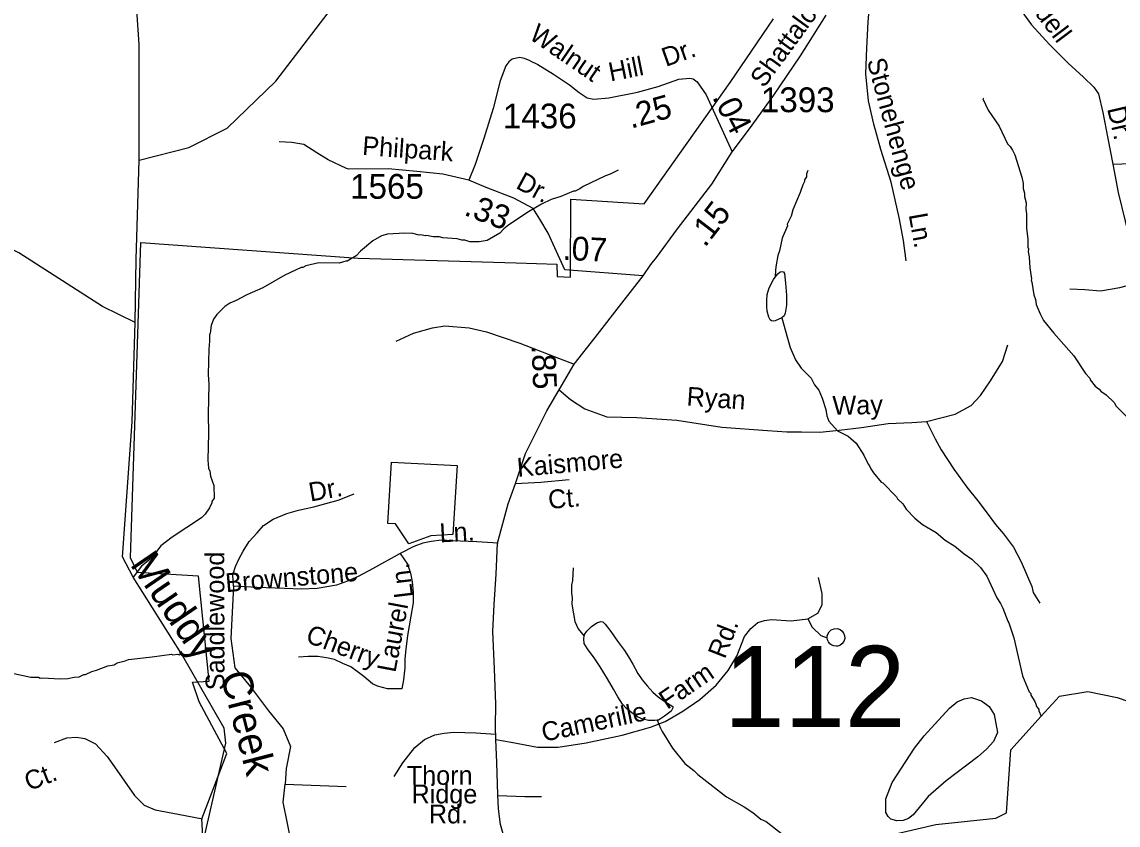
# Model space of a CAD drawing. Extents: x 1547597 to 1699558, y 810033 to 920809.
# Drawn here: x 1600633 to 1606161, y 869495 to 873547 of the extents above; entities that cross this region are included whole.
import ezdxf

# ---------------------------------------------------------------- set-up
doc = ezdxf.new("R2010")
doc.units = 0
for name, color, linetype in [('Exist Boundary Political City Limit New', 7, 'Continuous'), ('Exist Boundary Political City Limit New Hole', 7, 'Continuous'), ('Exist Hydrographic Creek Single Shore', 7, 'Continuous'), ('Exist Hydrographic Creek Single Shore Label', 7, 'Continuous'), ('Exist Hydrographic Misc Water Feature', 7, 'Continuous'), ('Exist Road Non-System Type 51', 7, 'Continuous'), ('Exist Road Non-System Type 51 Label', 7, 'Continuous'), ('Exist Road Secondary Mileage Hundredths English Label', 7, 'Continuous'), ('Exist Road Secondary Structure Standard Bridge Number Label', 7, 'Continuous'), ('Exist Road Secondary Type 51 Attributed', 7, 'Continuous'), ('Exist Road Secondary Type 51 Label', 7, 'Continuous'), ('Exist Road Secondary Type 51 Number Label', 7, 'Continuous'), ('Map Preparation Boundary City Limit Buffer Line', 7, 'Continuous')]:
    doc.layers.add(name, color=color, linetype=linetype)

msp = doc.modelspace()

# ---------------------------------------------------------------- linework, layer by layer
at = {"layer": 'Exist Boundary Political City Limit New'}
msp.add_lwpolyline([(1601575.9, 868902.4), (1601540.5, 869526.8), (1601665.9, 869856.2), (1601525.9, 870117.5), (1601493.2, 870216.5), (1601576.6, 870220.9), (1601523.9, 870750.7), (1601216.1, 870770.1), (1601180.3, 870843.5), (1601231.8, 872434), (1602327.7, 872355.7), (1603125.1, 872330.7), (1603330.7, 872325.5), (1603332.4, 872263.3), (1603399.8, 872259.8), (1603401.4, 872653.2), (1603771, 872629.9), (1604204.8, 873242), (1604423.6, 873562.3)], dxfattribs=at)
at = {"layer": 'Exist Boundary Political City Limit New Hole'}
msp.add_lwpolyline([(1602806.1, 870960.5), (1602694.2, 870955.1), (1602583.9, 870914.8), (1602516.1, 871014.5), (1602477.9, 871016.6), (1602497, 871326.1), (1602827.7, 871309.2), (1602806.1, 870960.5)], dxfattribs=at)
at = {"layer": 'Exist Hydrographic Creek Single Shore'}
for points in [[(1601223.6, 872849), (1601223.6, 873433.3), (1601181.7, 874057.9), (1601119.7, 874443.2), (1601022.7, 874625.7), (1600857.6, 874803)], [(1601223.6, 872849), (1601474.6, 872912.8), (1601667.7, 873010.7), (1601912.6, 873248.6), (1602379.6, 873859.6)], [(1601203.8, 872030.5), (1601038.7, 872110.7), (1600617.6, 872382), (1600244.6, 872570), (1599879.6, 872782.4), (1599289.7, 872825.8), (1599022.6, 872860.8), (1598839.6, 872831.7), (1598763.6, 872757.7), (1598635.7, 872550.2), (1598474.6, 872409.1), (1598248.6, 872328.3), (1597924.6, 872367.6), (1597665.7, 872330.2)], [(1601203.8, 872030.5), (1601208.7, 872350.2), (1601223.6, 872849)], [(1602782, 867111.8), (1602446.7, 867604.6), (1602229.1, 867924.7), (1602006.9, 868065), (1601866.6, 868242.5), (1601771.4, 868427.8), (1601611.7, 868773.7), (1601604.6, 868882.2), (1601579.7, 868899.1), (1601580.6, 868958.2), (1601556.6, 868985), (1601518.7, 869284.4), (1601660.7, 869908.5), (1601652.7, 869984.2), (1601436.5, 870359), (1601193.2, 870745.3), (1601139.7, 870848.1), (1601187.9, 871530), (1601203.8, 872030.5)], [(1604772.6, 869373), (1604858.4, 869409.8), (1605241.6, 869498.8), (1605544.1, 869530.6), (1605598.7, 869556.2), (1605619.6, 869874.2), (1605773, 870044.1), (1605865.7, 870145), (1606007.7, 870168.4), (1606156.7, 870139), (1606380.7, 870062.2), (1606464.7, 870086.8), (1606526.7, 870384.3)]]:
    msp.add_lwpolyline(points, dxfattribs=at)
at = {"layer": 'Exist Hydrographic Misc Water Feature'}
for points in [[(1605481.4, 873161.1), (1605478.9, 873158.3), (1605505.9, 873101.9), (1605560.7, 873020.9), (1605603.2, 872932.2), (1605617, 872918), (1605628.7, 872899.8), (1605640.2, 872875.7), (1605674.5, 872763.1), (1605682, 872731), (1605681.6, 872707), (1605689.1, 872682.8), (1605688.9, 872666.8), (1605696.4, 872634.7), (1605695.9, 872602.7), (1605699.5, 872578.6), (1605698.4, 872506.7), (1605705.4, 872450.6), (1605704.8, 872410.6), (1605708.6, 872402.5), (1605706.4, 872386.6), (1605712, 872362.5), (1605715.1, 872306.4), (1605724.2, 872250.2), (1605722.2, 872244.3), (1605726, 872234.3), (1605735, 872170.1), (1605744.5, 872146), (1605748.2, 872121.9), (1605767.4, 872073.6), (1605784.8, 872041.3), (1605835.8, 871976.4), (1605937.9, 871862.7), (1605996.4, 871773.7), (1606018.1, 871749.4), (1606019.9, 871741.3), (1606045.4, 871708.9), (1606065.2, 871694.6), (1606073, 871684.5), (1606100.7, 871665.9), (1606140.1, 871627.3), (1606151.7, 871609.1), (1606222.6, 871535.9)], [(1603640.1, 872799.4), (1603599.8, 872778), (1603575.6, 872770.5), (1603462.8, 872716.3), (1603446.6, 872704.6), (1603422.4, 872693), (1603414.5, 872693.2), (1603350, 872666.2), (1603301.8, 872651), (1603253.5, 872627.8), (1603186.9, 872589), (1603087.9, 872522.7), (1603063.6, 872503.1), (1603043.3, 872481.4), (1602978.7, 872444.5), (1602938.6, 872437.1), (1602890.6, 872438), (1602866.8, 872446.4), (1602850.8, 872446.7), (1602826.9, 872453), (1602755.1, 872458.3), (1602739.1, 872462.6), (1602707.2, 872463.1), (1602673.2, 872469.7), (1602667.2, 872467.7), (1602643.3, 872472.1), (1602635.3, 872470.3), (1602603.4, 872478.8), (1602563.5, 872481.4), (1602475.5, 872476.9), (1602445.3, 872467.5), (1602403, 872442.2), (1602340.1, 872391.2), (1602317.8, 872367.6), (1602273.4, 872340.4), (1602265.4, 872340.5), (1602233.2, 872329.1), (1602129.3, 872330.8), (1602065.1, 872315.9), (1602049, 872308.2), (1602041, 872308.3), (1601958.4, 872269.7), (1601847.4, 872205.5), (1601766.9, 872170.9), (1601712.5, 872141.9), (1601680.3, 872128.3), (1601656, 872110.8), (1601615.4, 872071.4), (1601599.1, 872047.8), (1601586.6, 872016), (1601581.9, 871976.1), (1601577.8, 871968.1), (1601579.3, 871936.1), (1601574.6, 871896.2), (1601572.6, 871768.3), (1601575.8, 871720.2), (1601571.4, 871568.2), (1601573.9, 871472.3), (1601569.7, 871336.3), (1601573, 871296.2), (1601580.7, 871280.1), (1601584.4, 871256), (1601599.6, 871207.9), (1601602.6, 871143.8), (1601590.4, 871128), (1601590.2, 871120), (1601577.9, 871096.2), (1601557.3, 871064.5), (1601539, 871044.8), (1601389.5, 870947.3), (1601332.9, 870904.4), (1601285.9, 870841.1), (1601235.5, 870801), (1601193.2, 870745.3)], [(1604595.5, 872797.2), (1604589.2, 872781.3), (1604589, 872765.3), (1604578.8, 872749.5), (1604578.7, 872741.5), (1604570.4, 872725.7), (1604557.8, 872685.9), (1604520.4, 872598.5), (1604511.8, 872566.6), (1604491.2, 872527.1), (1604493.2, 872519), (1604466.1, 872455.4), (1604453.1, 872391.6), (1604444.8, 872367.8), (1604436, 872322), (1604433.7, 872296.7), (1604431.7, 872258.9)], [(1604431.7, 872258.9), (1604444.3, 872276.3), (1604457.3, 872286.9), (1604466.4, 872288.5), (1604472.7, 872285.9), (1604477.6, 872278.4), (1604483.6, 872229.6), (1604489.1, 872168.9), (1604487.6, 872118.2), (1604482.2, 872077.9), (1604476.3, 872063.9), (1604464.6, 872054.7)], [(1604464.6, 872054.7), (1604431.5, 872039), (1604421.5, 872037.5), (1604412.8, 872038.8), (1604406.5, 872043.6), (1604399.7, 872057.3), (1604391.3, 872088.2), (1604389.1, 872111.9), (1604388.6, 872142.3), (1604391.1, 872171.4), (1604401.4, 872205.7), (1604423.2, 872247.1), (1604431.7, 872258.9)], [(1604464.6, 872054.7), (1604493, 871951.7), (1604507.3, 871904.8), (1604534.3, 871842.4), (1604561.6, 871800), (1604612.7, 871749.1), (1604630.3, 871716.8), (1604651.8, 871688.4), (1604669.1, 871648.1), (1604686.2, 871591.8), (1604691.7, 871559.7), (1604701.3, 871533.6), (1604746.4, 871484.8), (1604800, 871457.9), (1604839.4, 871421.2), (1604878.4, 871360.6), (1604899.7, 871316.2), (1604907.6, 871308.1), (1604913.3, 871292), (1604927, 871271.8), (1604966.2, 871225.2), (1604974.1, 871221), (1605043, 871151.9), (1605048.9, 871141.7), (1605074.4, 871115.3), (1605091.9, 871089), (1605135.2, 871044.3), (1605174.7, 871011.6), (1605244, 870970.5), (1605289.3, 870931.8), (1605336.9, 870902.9), (1605384.2, 870864.1), (1605423.8, 870837.4), (1605467.1, 870794.8), (1605498.3, 870750.2), (1605548.6, 870641.4), (1605568.1, 870613.1), (1605579.8, 870588.9), (1605604.7, 870524.4), (1605610.5, 870516.3), (1605635.3, 870439.9), (1605678.2, 870247.3), (1605712.9, 870166.7), (1605720.7, 870158.5), (1605720.6, 870150.5), (1605740.1, 870118.2), (1605747.9, 870102.1), (1605747.8, 870096.1), (1605761.4, 870077.8), (1605761.3, 870071.9), (1605773, 870044.1)], [(1603412, 870793.3), (1603409.1, 870729.4), (1603404.7, 870705.5), (1603404, 870665.5), (1603407.6, 870641.4), (1603405.2, 870609.5), (1603414.4, 870561.3), (1603421.1, 870521.6), (1603437.6, 870485), (1603468, 870448.2)], [(1603468, 870448.2), (1603469.5, 870457.2), (1603481.5, 870474), (1603504.6, 870497.5), (1603531.2, 870515.8), (1603551.6, 870522.3), (1603561.7, 870520.4), (1603574.3, 870509.2), (1603601.8, 870471.6), (1603636, 870422.9), (1603671, 870375.9), (1603691.8, 870343.4), (1603713.4, 870307.5), (1603738.3, 870259.7), (1603760.7, 870227.2), (1603785, 870198.1), (1603814.3, 870165.5), (1603841.1, 870141.4), (1603874.7, 870118.9), (1603915.1, 870093), (1603915.9, 870087), (1603906.3, 870070.2), (1603873.8, 870045.2), (1603842.2, 870024.4), (1603836.5, 870023.7)], [(1603836.5, 870023.7), (1603824.4, 870022.1), (1603793, 870023.4), (1603764.3, 870029.6), (1603737.4, 870041), (1603708.8, 870060.8), (1603681.9, 870084.1), (1603661.9, 870105.5), (1603638.5, 870142.3), (1603615.4, 870181.6), (1603586.2, 870232.7), (1603548.8, 870294.3), (1603518.9, 870338.7), (1603484.6, 870384.1), (1603468, 870411.4), (1603465.8, 870434.4), (1603468, 870448.2)], [(1600577, 870263.2), (1600676.7, 870241.5), (1600716.5, 870240.8), (1600724.5, 870236.6), (1600738.6, 870238.4), (1600824.4, 870232.9), (1600864.4, 870234.3), (1600896.5, 870241.8), (1600920.6, 870243.4), (1600944.7, 870255), (1600952.7, 870254.8), (1600984.9, 870270.3), (1601009, 870275.9), (1601065.3, 870298.9), (1601097.4, 870304.4), (1601113.5, 870314.1), (1601153.7, 870323.5), (1601169.8, 870331.2), (1601290, 870343.2), (1601386.1, 870357.5), (1601394, 870353.4), (1601418.1, 870357), (1601426, 870354.8), (1601436.5, 870359)], [(1605456.4, 870127.2), (1605471.5, 870122.7), (1605510.9, 870093.8), (1605535.9, 870053.2), (1605551.7, 869962.8), (1605532.5, 869917.3), (1605497.5, 869878.1), (1605452.6, 869839.2), (1605293.6, 869719.1), (1605203.6, 869639.2), (1605127.4, 869547), (1605102.9, 869527.7), (1605076.7, 869518.3), (1605044.6, 869517.1), (1605014.8, 869525.8), (1605001.1, 869538.1), (1604989.6, 869558.4), (1604989.3, 869628.4), (1605021.3, 869709.6), (1605133.6, 869882.9), (1605183.2, 869945.8), (1605310.5, 870084.7), (1605349.4, 870117.7), (1605383.7, 870132.9), (1605421.9, 870138), (1605456.4, 870127.2)], [(1603836.5, 870023.7), (1603852.9, 869984), (1603860.6, 869967.9), (1603913.3, 869883), (1603976, 869805.9), (1604021.5, 869771.2), (1604041, 869750.9), (1604185.2, 869638.5), (1604274.4, 869586.9), (1604317.9, 869558.2), (1604359.3, 869525.5), (1604385.1, 869513.1), (1604495.6, 869427.2), (1604519.2, 869400.8), (1604540.5, 869360.4), (1604567.5, 869322.3)]]:
    msp.add_lwpolyline(points, dxfattribs=at)
at = {"layer": 'Exist Road Non-System Type 51'}
msp.add_line((1601960.6, 869701.2), (1602267.3, 869690.6), dxfattribs=at)
for points in [[(1605004.4, 874193.8), (1605073.8, 874129.1), (1605183, 874056.2), (1605332.3, 873991), (1605420, 873944.3), (1605453.7, 873918), (1605501.2, 873861.6), (1605590.1, 873727), (1605661.2, 873618.5), (1605724.4, 873531.9), (1605815.5, 873433.2), (1605908.6, 873338.5), (1605986, 873267.8), (1606037.6, 873217.4), (1606061.4, 873183.3), (1606084.5, 873089.1), (1606109.4, 872959), (1606134.4, 872828.8)], [(1605091.1, 872341.7), (1605077.8, 872443.6), (1605056.9, 872559.9), (1605016.3, 872738), (1604963.6, 872902.4), (1604928.8, 873030.8), (1604901.8, 873148.8), (1604888.9, 873284.9), (1604894, 873414.9), (1604901.1, 873546.6), (1604907.9, 873646.6), (1604900.7, 873744.6), (1604880.5, 873889.2)], [(1603196, 873349.9), (1603166.8, 873363.1), (1603142.6, 873367.4), (1603105.2, 873358.6), (1603087.3, 873344.7), (1603072.3, 873326), (1603043.8, 873250.2), (1603008.7, 873110.6), (1602961.4, 872959.1), (1602918.5, 872827.5), (1602885.9, 872747.7)], [(1602269.4, 872807.1), (1602177.2, 872851.5), (1602119.5, 872885.9), (1602053.9, 872928.5), (1601993.9, 872939.1), (1601930.1, 872941.6)], [(1606134.4, 872828.8), (1606318.2, 872835.2), (1606548.2, 872845.4)], [(1606134.4, 872828.8), (1606161.1, 872686.6), (1606196, 872542.4), (1606238.5, 872366.2), (1606265.4, 872232)], [(1605917.3, 872200.8), (1605993.3, 872196.3), (1606071.2, 872189.5), (1606169.2, 872206.7), (1606265.4, 872232)], [(1602519.4, 871937), (1602607.7, 871976.3), (1602703.9, 872003.5), (1602765.9, 872012.9), (1602887.8, 872004), (1602975.4, 871983.2), (1603143, 871926), (1603316.3, 871858.4), (1603417.5, 871820.3)], [(1605193.8, 871531.5), (1605338.6, 871567.8), (1605418.9, 871611.2), (1605467.2, 871662.8), (1605517.9, 871736.2), (1605578.5, 871833.9), (1605605.2, 871917.6)], [(1603341.8, 871690.4), (1603398.6, 871641.7), (1603471.6, 871595.7), (1603582.5, 871555.1), (1603733, 871551.7), (1603934.7, 871538), (1604161.6, 871502.2), (1604393.4, 871486.3), (1604490.9, 871479.4), (1604563.9, 871479.4), (1604655.9, 871476.6), (1604753.2, 871487.5), (1604866.8, 871501), (1605000.4, 871520.6), (1605120.4, 871525.6), (1605193.8, 871531.5)], [(1605193.8, 871531.5), (1605238, 871443), (1605268.3, 871387.8), (1605331.9, 871291), (1605398.1, 871199.8), (1605453.4, 871130.7), (1605500.7, 871068.7), (1605541.8, 871011.8), (1605583.2, 870964.8), (1605632.8, 870896.9), (1605672.4, 870822.6), (1605725.1, 870699), (1605732.9, 870669), (1605766.5, 870614.7)], [(1603121.4, 871217.8), (1603249, 871225.2), (1603393.1, 871238.1)], [(1601699, 870700), (1601696.1, 870757.3), (1601710.4, 870800.2), (1601727.6, 870840.3), (1601747.6, 870877.5), (1601779.1, 870926.1), (1601819.1, 870969), (1601850.6, 871006.3), (1601899.2, 871037.7), (1601967.9, 871066.4), (1602027.9, 871083.5), (1602105.2, 871100.7), (1602165.2, 871117.9), (1602228.1, 871135), (1602308.2, 871166.5)], [(1603034.7, 870917.5), (1602926.1, 870923.3), (1602803.1, 870929), (1602748.7, 870931.8), (1602697.2, 870926.1), (1602654.3, 870917.5), (1602608.6, 870900.4), (1602539.9, 870866)], [(1602539.9, 870866), (1602399.8, 870788.7), (1602328.3, 870748.7), (1602273.9, 870725.8), (1602219.6, 870705.7), (1602170.9, 870697.2), (1602122.3, 870688.6), (1602042.2, 870685.7), (1601956.4, 870688.6), (1601819.1, 870694.3), (1601699, 870700)], [(1602539.9, 870866), (1602577.1, 870811.6), (1602591.4, 870765.8), (1602600, 870722.9), (1602605.7, 870668.5), (1602605.7, 870617), (1602594.3, 870548.3), (1602577.1, 870451), (1602568.5, 870382.3), (1602562.8, 870333.7), (1602562.8, 870287.9), (1602557.1, 870227.8), (1602548.5, 870182), (1602477, 870182), (1602425.5, 870196.3), (1602399.8, 870207.7), (1602356.9, 870245), (1602322.5, 870270.7), (1602291.1, 870293.6), (1602251, 870310.8), (1602208.1, 870330.8), (1602168.1, 870339.4), (1602125.2, 870345.1), (1602076.6, 870345.1), (1602027.9, 870342.3)], [(1604596.6, 870536.4), (1604646.8, 870564), (1604669, 870605.8), (1604667.6, 870663.7), (1604650.2, 870743.9)], [(1601699, 870700), (1601685.7, 870436.7), (1601706.8, 870288.6), (1601786.1, 870193.3), (1601876, 870071.6), (1601950, 869981.6), (1601987, 869891.7), (1601965.9, 869780.6), (1601960.6, 869701.2)], [(1603023.1, 869926.4), (1603100.5, 869913), (1603232, 869887.9), (1603336.1, 869889), (1603478.2, 869910), (1603660.3, 869948.3), (1603802.6, 869989.2), (1603876.9, 870018.5), (1603965.2, 870069.8), (1604051.6, 870129.1), (1604134.1, 870200.4), (1604194.7, 870275.8), (1604237.2, 870347.4), (1604276, 870447.1), (1604308.4, 870486.9), (1604344.6, 870516.5), (1604378.3, 870527.3), (1604412.6, 870532), (1604512.5, 870525.1), (1604596.6, 870536.4)], [(1604596.6, 870536.4), (1604618.1, 870494.2), (1604661.9, 870451.9), (1604693.7, 870439.6)], [(1604693.7, 870439.6), (1604693.8, 870447.6), (1604696.3, 870458), (1604702.9, 870469.6), (1604714.3, 870480), (1604728.8, 870485.9), (1604743.3, 870486.4), (1604759.4, 870481.1), (1604769, 870473.7), (1604776.6, 870463.9), (1604781.4, 870452), (1604782.3, 870436.4), (1604777.8, 870421.3), (1604768.3, 870409.3), (1604756.8, 870401.7), (1604747.1, 870398.3), (1604739.1, 870397.5), (1604726.5, 870398.7), (1604716.6, 870402.9), (1604706.3, 870410.3), (1604699.5, 870419.1), (1604695.3, 870429), (1604693.7, 870439.6)], [(1602509.5, 869740.1), (1602554.1, 869809.6), (1602614.7, 869887.2), (1602663, 869926.7), (1602715.1, 869950.4), (1602761.3, 869958.5), (1602811.2, 869963.5), (1602921, 869960.7), (1603022.4, 869953.2)], [(1600797.6, 869912), (1600859.7, 869935.5), (1600907.6, 869939.2), (1600949.5, 869932.7), (1601003.3, 869904.4), (1601062.7, 869842), (1601099.5, 869789.5), (1601201, 869644.8), (1601248.6, 869596.4), (1601304.4, 869571.9), (1601420.2, 869550.9), (1601543.8, 869526)], [(1602378.2, 868906.5), (1602270.1, 868964), (1602204, 869004.2), (1602162, 869041.8), (1602121.5, 869089.1), (1602082.5, 869140.3), (1602058, 869180.5), (1602041.2, 869211.7), (1602022.7, 869270), (1602008.9, 869328.8), (1601994.4, 869395.7), (1601950, 869611.2), (1601960.6, 869701.2)], [(1603033.1, 869644.2), (1603169, 869640), (1603253.4, 869638.7)]]:
    msp.add_lwpolyline(points, dxfattribs=at)
at = {"layer": 'Exist Road Secondary Type 51 Attributed'}
for points in [[(1604213.6, 872892), (1604301.8, 873007.4), (1604424.3, 873176.9), (1604559.8, 873375.7), (1604687.8, 873580.9)], [(1603196, 873349.9), (1603234.4, 873332.5), (1603313.8, 873283.9), (1603393.4, 873229.3), (1603443, 873190.8), (1603482.9, 873164.6), (1603516.8, 873156.3), (1603592.7, 873163.8), (1603736.8, 873192.5), (1603841.1, 873221.6), (1603945.3, 873258.7), (1604000.1, 873263.1), (1604017.5, 873259), (1604038.4, 873244.6), (1604083.8, 873178.4), (1604213.6, 872892)], [(1603765.7, 872265.2), (1603804.2, 872322.9), (1603833.1, 872358.4), (1603939, 872503), (1604112.4, 872727.9), (1604213.6, 872892)], [(1603765.7, 872265.2), (1603370.9, 872296.8), (1603287.3, 872480.5), (1603244.2, 872552.3), (1603210.4, 872605), (1603113, 872657.8), (1602973.4, 872711.1), (1602885.9, 872747.7), (1602756.1, 872778.7), (1602624.4, 872792.2), (1602479.3, 872806.2), (1602280.8, 872804.5), (1602269.4, 872807.1)], [(1603071, 869409.9), (1603046.3, 869497.9), (1603035.7, 869577.4), (1603032.9, 869648.2), (1603027.5, 869810.3), (1603023.1, 869926.2), (1603021.3, 869993.2), (1603022.1, 870105.5), (1603015.6, 870283.6), (1603007, 870471.5), (1603014.6, 870608.8), (1603023.9, 870761), (1603031.2, 870917.3), (1603084.9, 871115.9), (1603121.4, 871217.8), (1603171.5, 871370.3), (1603279.6, 871584.9), (1603341.8, 871690.4), (1603417.5, 871820.3), (1603523, 871954.8), (1603658.2, 872128), (1603765.7, 872265.2)]]:
    msp.add_lwpolyline(points, dxfattribs=at)
at = {"layer": 'Map Preparation Boundary City Limit Buffer Line'}
msp.add_lwpolyline([(1601575.9, 868902.4), (1601540.5, 869526.8), (1601665.9, 869856.2), (1601525.9, 870117.5), (1601493.2, 870216.5), (1601576.6, 870220.9), (1601523.9, 870750.7), (1601216.1, 870770.1), (1601180.3, 870843.5), (1601231.8, 872434), (1602327.7, 872355.7), (1603125.1, 872330.7), (1603330.7, 872325.5), (1603332.4, 872263.3), (1603399.8, 872259.8), (1603401.4, 872653.2), (1603771, 872629.9), (1604204.8, 873242), (1604423.6, 873562.3)], dxfattribs=at)

# ---------------------------------------------------------------- texts
at = {"layer": 'Exist Hydrographic Creek Single Shore Label'}
for s, rotation, p in [('Muddy', 304.3856, (1601174.3, 870810)), ('Creek', 284.4455, (1601633.2, 870253.5))]:
    msp.add_text(s, height=150, rotation=rotation, dxfattribs=at).set_placement(p)
at = {"layer": 'Exist Road Non-System Type 51 Label'}
for s, rotation, p in [('Sunnydell', 307.0617, (1605520, 873878.5)), ('Stonehenge', 285.1732, (1604892.9, 873351.3)), ('Dr.', 283.2011, (1606104.7, 873109.6)), ('Ln.', 280.166, (1605104.3, 872574.7)), ('Ryan', 356.0724, (1603982.7, 871611.7)), ('Way', 1.1296, (1604721.2, 871564.3)), ('Kaismore', 5.1063, (1603133.2, 871251.7)), ('Dr.', 10.105, (1602087.9, 871127)), ('Ct.', 5.1063, (1603290.6, 871089.5)), ('Ln.', 3.062, (1602740.9, 870921.2)), ('Saddlewood', 90.1256, (1601654.2, 870175.4)), ('Brownstone', 4.9617, (1601662.6, 870669.8)), ('Ln.', 97.0336, (1602605.6, 870646.2)), ('Laurel', 79.323, (1602515.9, 870261.3)), ('Cherry', 339.43, (1602057.8, 870420.3)), ('Rd.', 68.707, (1604177.4, 870329.5)), ('Farm', 34.4371, (1603887, 870075.8)), ('Camerille', 11.8867, (1603263.7, 869915.1))]:
    msp.add_text(s, height=95, rotation=rotation, dxfattribs=at).set_placement(p)
for s, p in [('Thorn', (1602573.4, 869698.7)), ('Ridge', (1602597.4, 869604.7)), ('Rd.', (1602684.9, 869503.8))]:
    msp.add_text(s, height=95, dxfattribs=at).set_placement(p)
at = {"layer": 'Exist Road Secondary Mileage Hundredths English Label'}
for s, rotation, p in [('.25', 15.5966, (1603704.5, 873007.8)), ('.04', 296.928, (1604111.8, 873168)), ('.33', 339.1144, (1602856.8, 872574.5)), ('.15', 52.3761, (1604077.3, 872405.2)), ('.07', 357.0466, (1603357.9, 872347.5)), ('.85', 272.1191, (1603203, 871914.3))]:
    msp.add_text(s, height=120, rotation=rotation, dxfattribs=at).set_placement(p)
at = {"layer": 'Exist Road Secondary Structure Standard Bridge Number Label'}
msp.add_text('112', height=410.1, dxfattribs=at).set_placement((1604173.3, 869989.3))
at = {"layer": 'Exist Road Secondary Type 51 Label'}
for s, rotation, p in [('Shattalon', 53.8885, (1604374.8, 873209.8)), ('Walnut', 325.5065, (1603184.6, 873465.1)), ('Dr.', 19.4966, (1603879.8, 873319.6)), ('Hill', 11.2633, (1603601, 873246)), ('Philpark', 355.9386, (1602347, 872876.1)), ('Dr.', 331.5298, (1603118.2, 872711)), ('Ct.', 21.3168, (1600667.6, 869666.1))]:
    msp.add_text(s, height=95, rotation=rotation, dxfattribs=at).set_placement(p)
at = {"layer": 'Exist Road Secondary Type 51 Number Label'}
for s, p in [('1393', (1604359.3, 873091.5)), ('1436', (1603058.5, 873009.8)), ('1565', (1602287.7, 872654.8))]:
    msp.add_text(s, height=125, dxfattribs=at).set_placement(p)

doc.saveas('drawing.dxf')
